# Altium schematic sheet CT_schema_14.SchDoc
size 519 x 434 mm
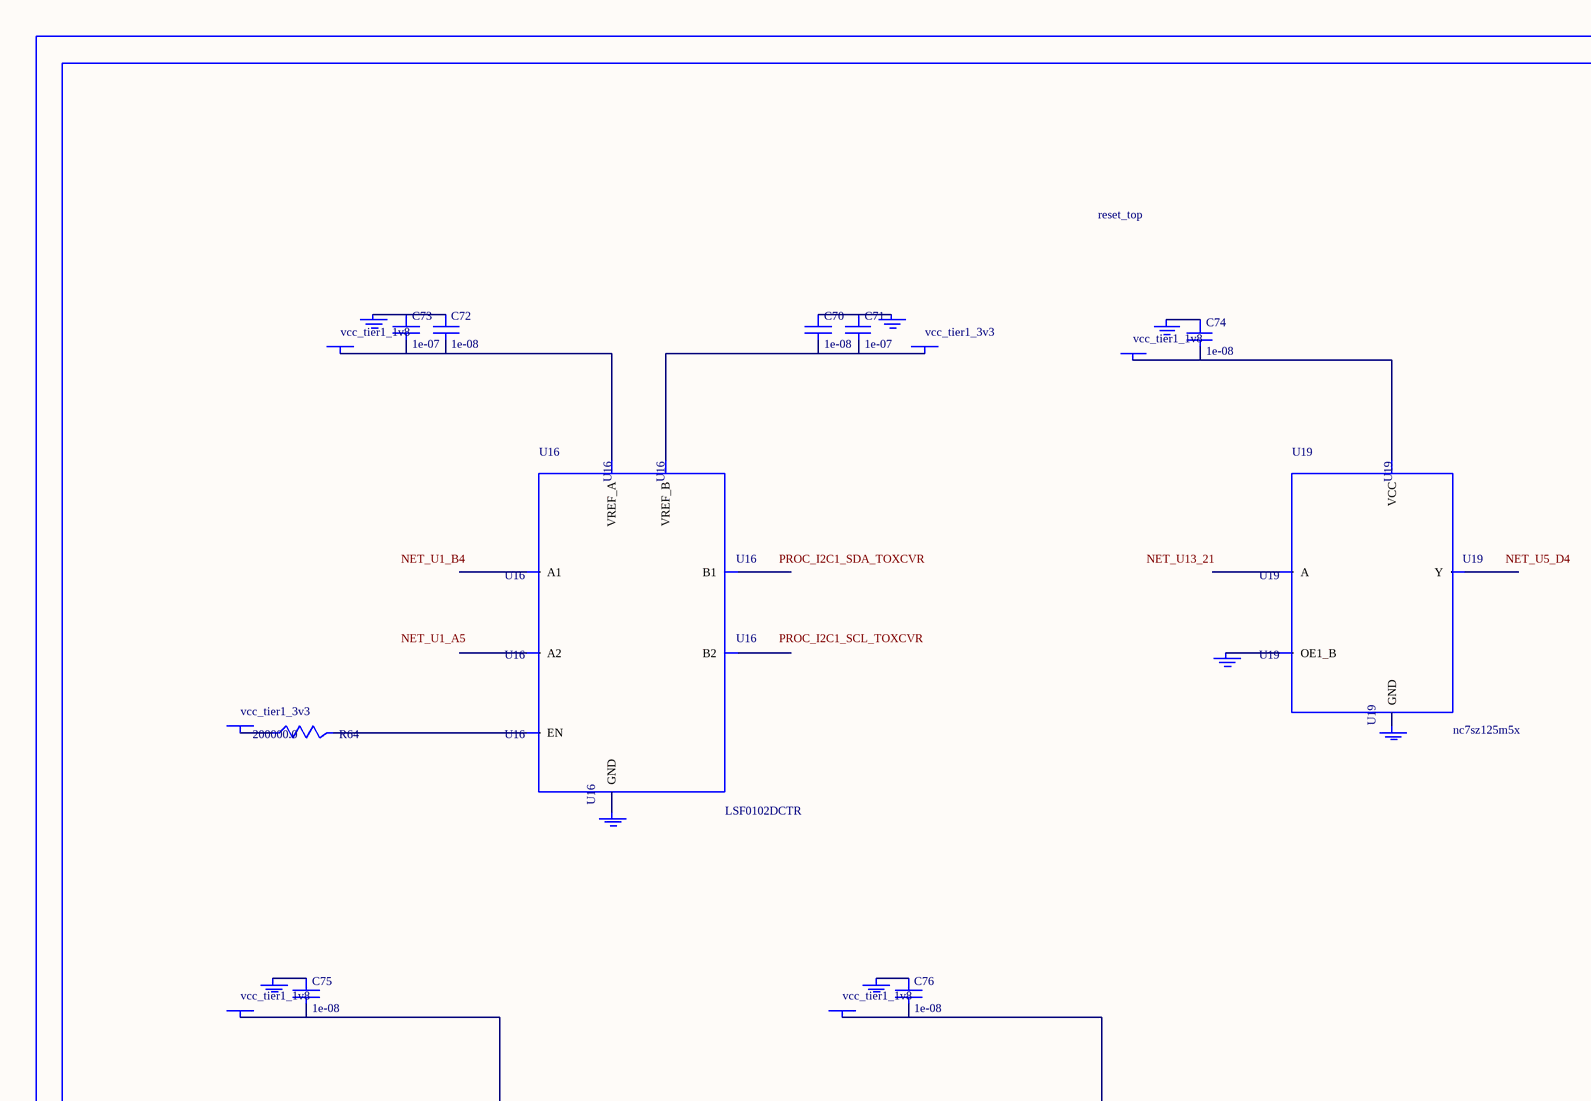
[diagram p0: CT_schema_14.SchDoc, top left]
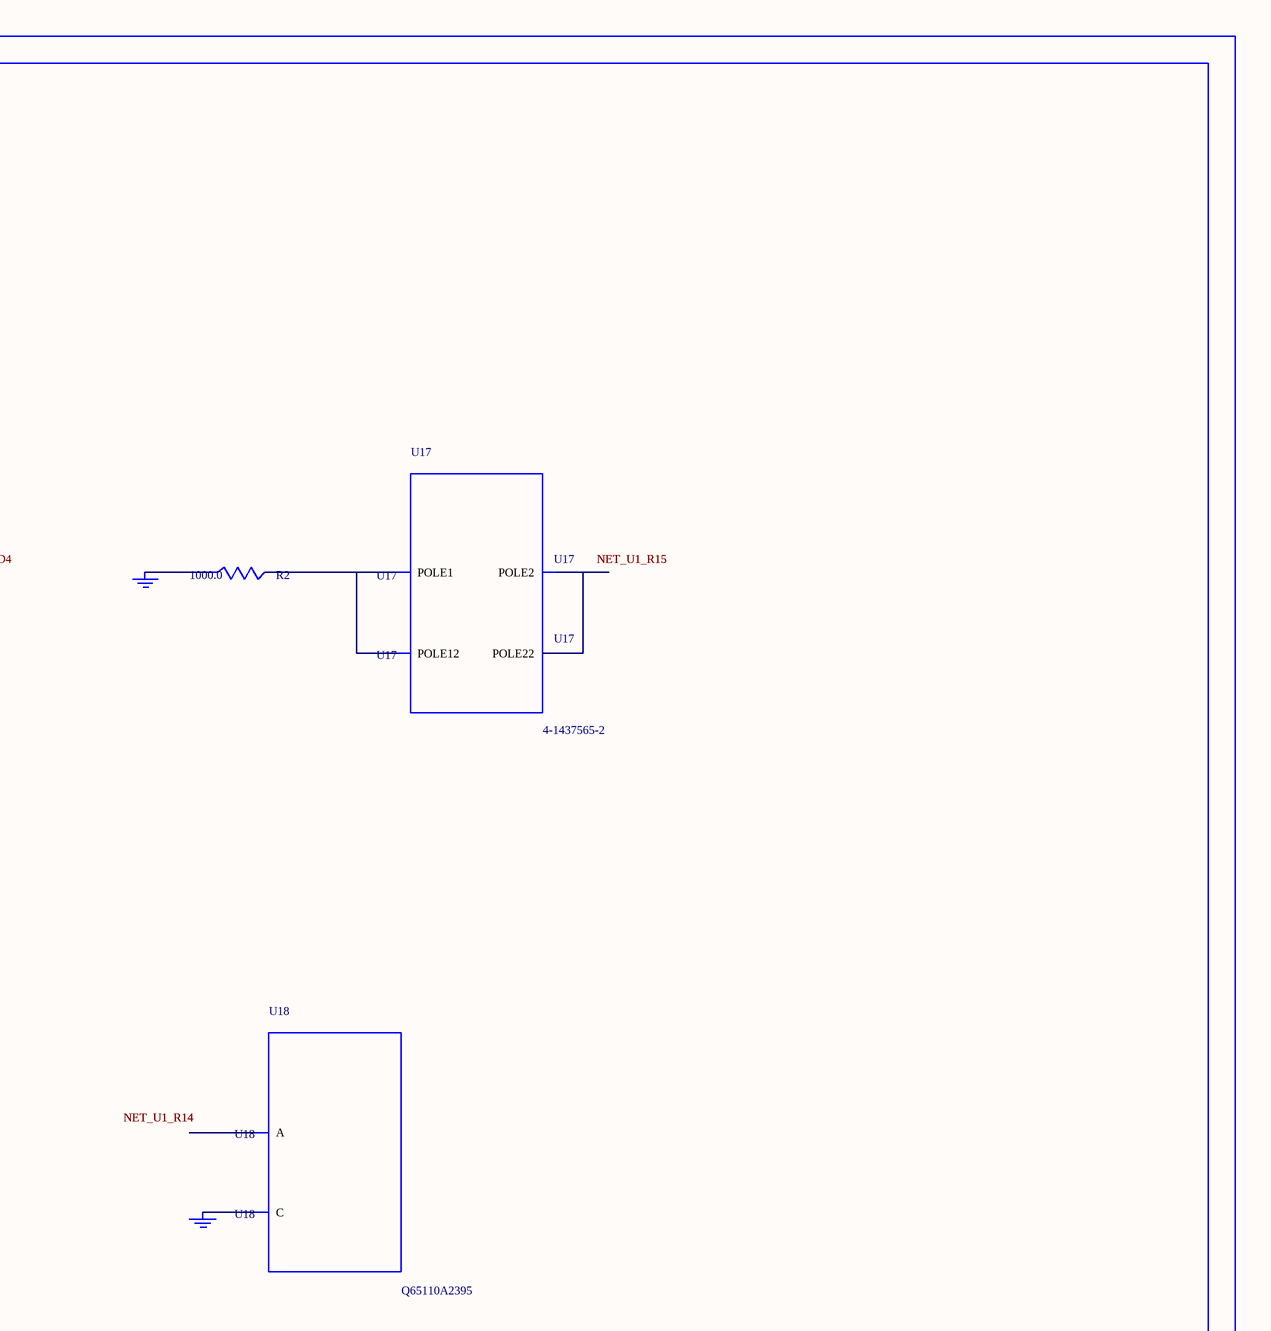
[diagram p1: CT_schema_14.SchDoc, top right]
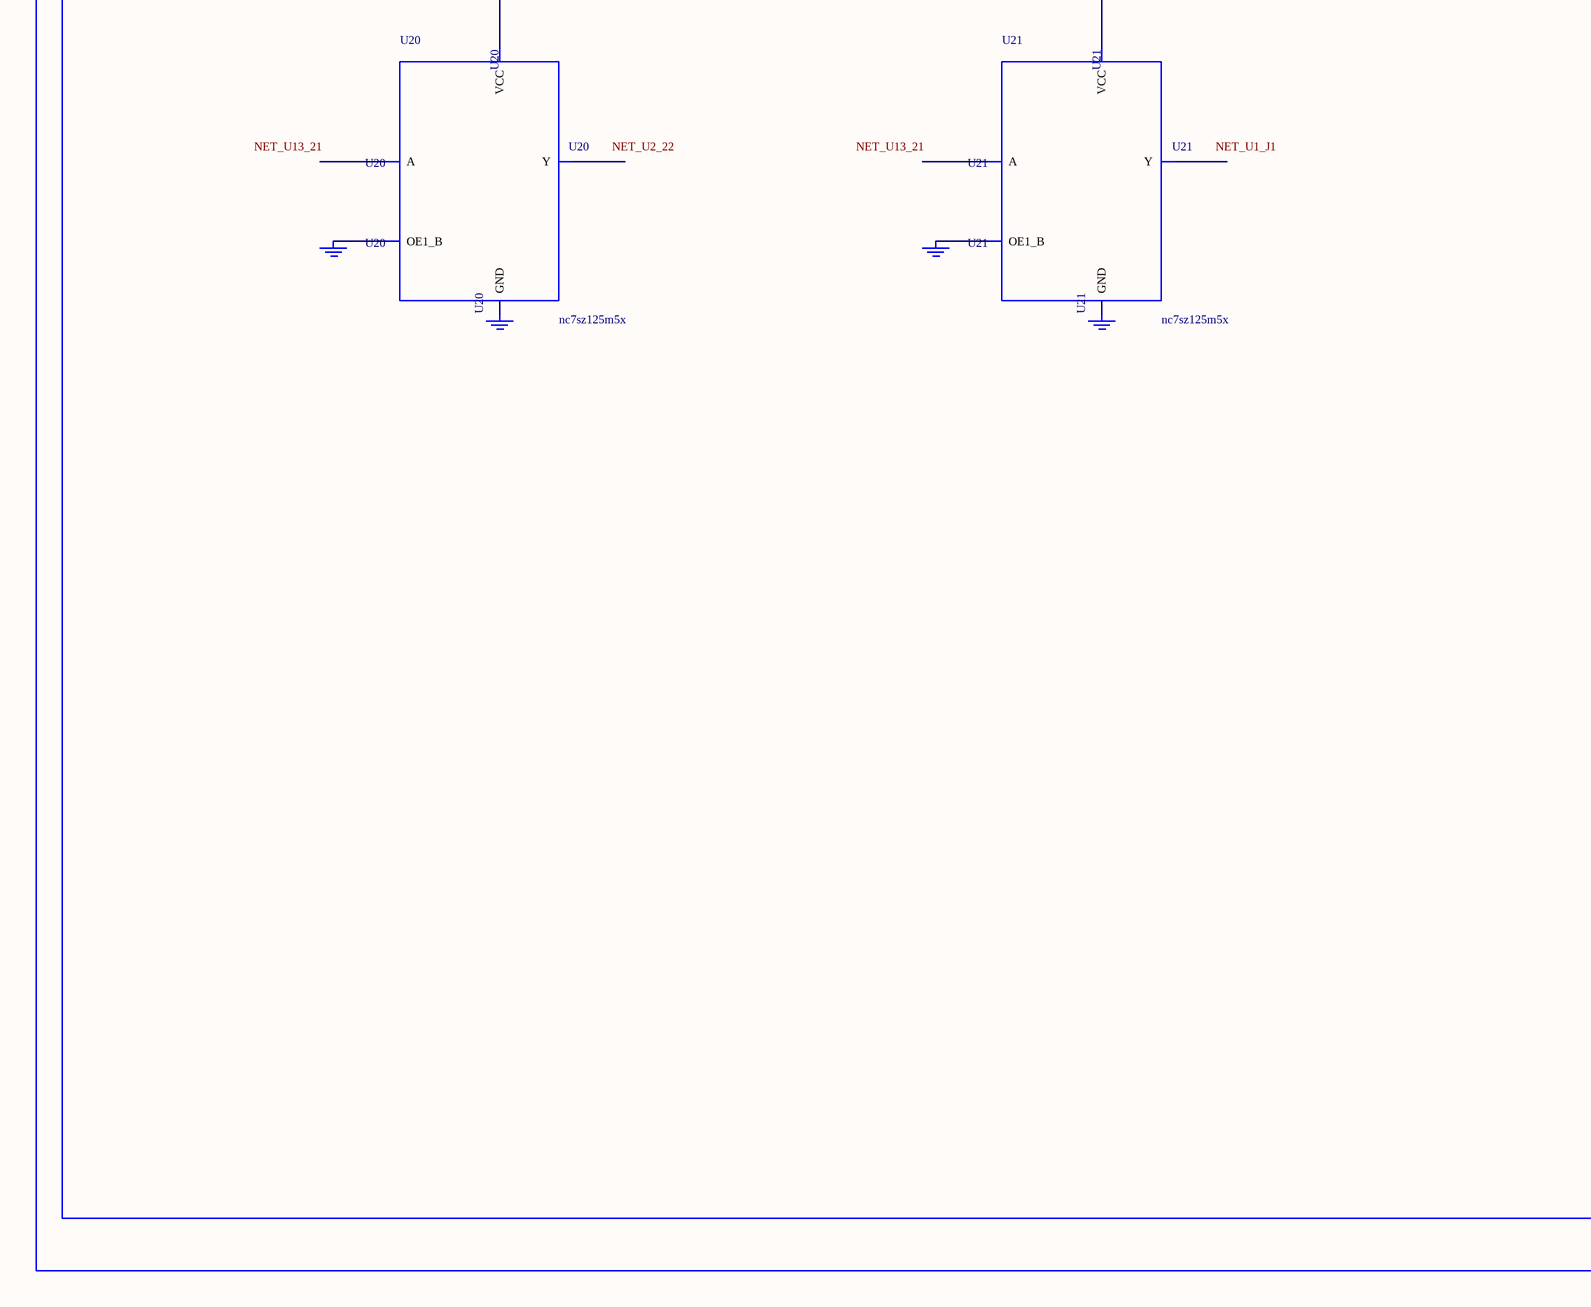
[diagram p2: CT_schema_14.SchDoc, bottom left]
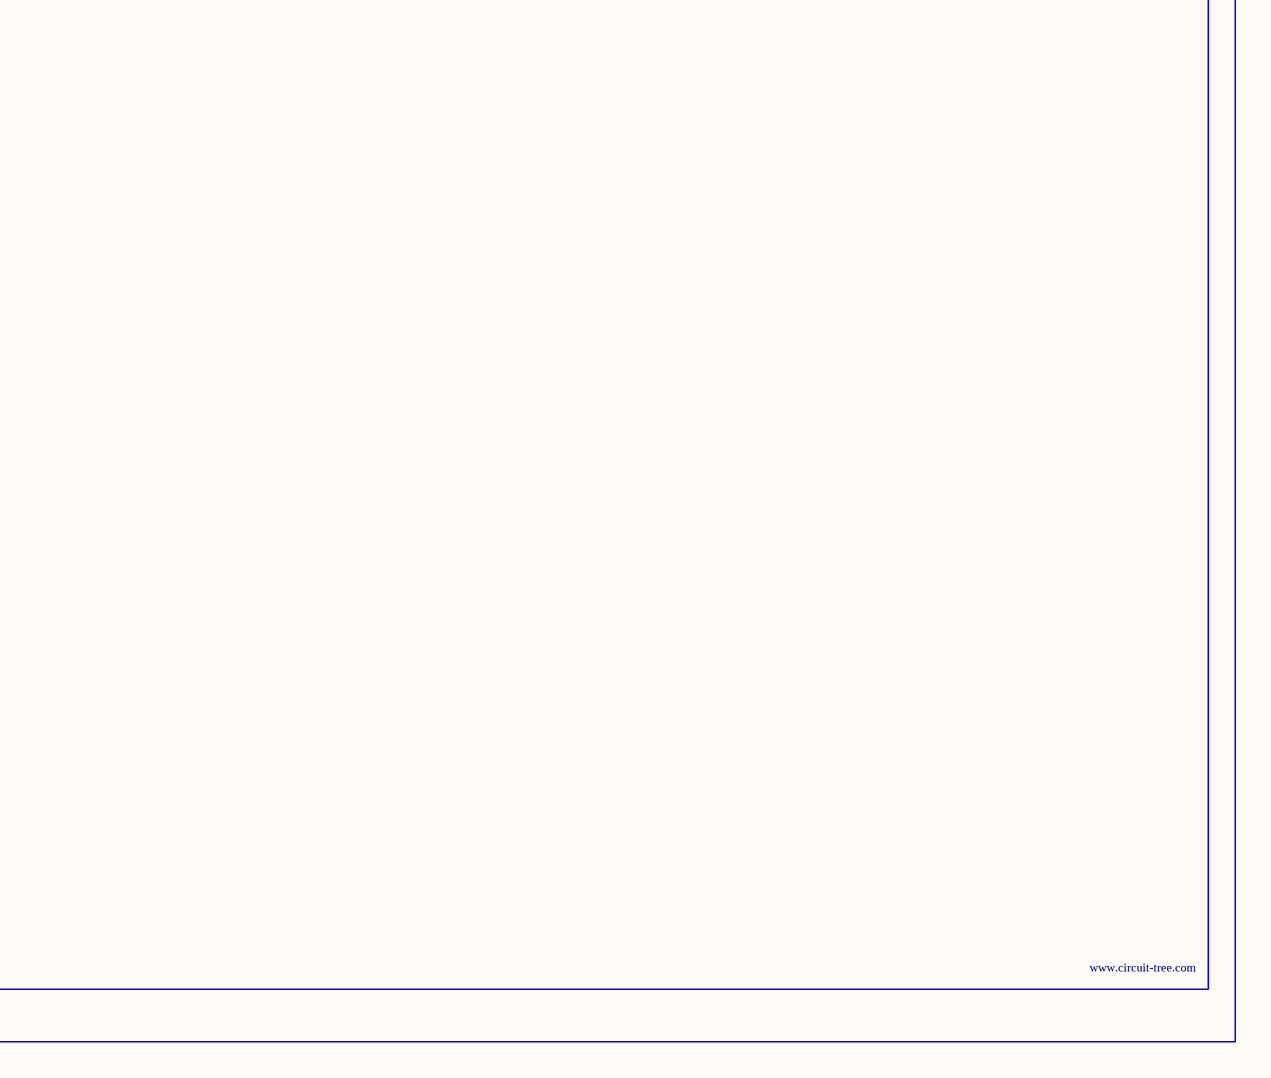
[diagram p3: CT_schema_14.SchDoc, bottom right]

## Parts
BORDER13  (no value)
C70  1e-08  [C0402]
C71  1e-07  [C0402]
C72  1e-08  [C0402]
C73  1e-07  [C0402]
C74  1e-08  [C0402]
C75  1e-08  [C0402]
C76  1e-08  [C0402]
GND_INSTANCE_13_0  (no value)
GND_INSTANCE_13_1  (no value)
GND_INSTANCE_13_2  (no value)
GND_INSTANCE_13_3  (no value)
GND_INSTANCE_13_4  (no value)
GND_INSTANCE_13_5  (no value)
GND_INSTANCE_13_6  (no value)
GND_INSTANCE_13_7  (no value)
GND_INSTANCE_13_8  (no value)
GND_INSTANCE_13_9  (no value)
GND_INSTANCE_13_10  (no value)
GND_INSTANCE_13_11  (no value)
GND_INSTANCE_13_12  (no value)
GND_INSTANCE_13_13  (no value)
POWER_INSTANCE_13_0  vcc_tier1_1v8
POWER_INSTANCE_13_1  vcc_tier1_3v3
POWER_INSTANCE_13_2  vcc_tier1_3v3
POWER_INSTANCE_13_3  vcc_tier1_1v8
POWER_INSTANCE_13_4  vcc_tier1_1v8
POWER_INSTANCE_13_5  vcc_tier1_1v8
R2  1000.0  [R0603]
R64  200000.0  [R0603]
U16  LSF0102DCTR  [DCU0008A_N]
U17  4-1437565-2  [SW_4-1437565-2]
U18  Q65110A2395  [LGM67K-G1J2-24-Z]
U19  nc7sz125m5x  [NC7SZ125M5X]
U20  nc7sz125m5x  [NC7SZ125M5X]
U21  nc7sz125m5x  [NC7SZ125M5X]

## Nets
NetC70_1: C70.1 C71.1 GND_INSTANCE_13_1.0(GND)
NetC70_2: C70.2 C71.2 POWER_INSTANCE_13_1.0(PWR) U16.7(VREF_B)
NetC72_1: C72.1 C73.1 GND_INSTANCE_13_0.0(GND)
NetC72_2: C72.2 C73.2 POWER_INSTANCE_13_0.0(PWR) U16.2(VREF_A)
NetC74_1: C74.1 GND_INSTANCE_13_5.0(GND)
NetC74_2: C74.2 POWER_INSTANCE_13_3.0(PWR) U19.5(VCC)
NetC75_1: C75.1 GND_INSTANCE_13_8.0(GND)
NetC75_2: C75.2 POWER_INSTANCE_13_4.0(PWR) U20.5(VCC)
NetC76_1: C76.1 GND_INSTANCE_13_11.0(GND)
NetC76_2: C76.2 POWER_INSTANCE_13_5.0(PWR) U21.5(VCC)
NetGND_INSTANCE_13_2_0: GND_INSTANCE_13_2.0(GND) U16.1(GND)
NetGND_INSTANCE_13_3_0: GND_INSTANCE_13_3.0(GND) R2.1
NetGND_INSTANCE_13_4_0: GND_INSTANCE_13_4.0(GND) U18.C
NetGND_INSTANCE_13_6_0: GND_INSTANCE_13_6.0(GND) U19.1(OE1_B)
NetGND_INSTANCE_13_7_0: GND_INSTANCE_13_7.0(GND) U19.3(GND)
NetGND_INSTANCE_13_9_0: GND_INSTANCE_13_9.0(GND) U20.1(OE1_B)
NetGND_INSTANCE_13_10_0: GND_INSTANCE_13_10.0(GND) U20.3(GND)
NetGND_INSTANCE_13_12_0: GND_INSTANCE_13_12.0(GND) U21.1(OE1_B)
NetGND_INSTANCE_13_13_0: GND_INSTANCE_13_13.0(GND) U21.3(GND)
NetPOWER_INSTANCE_13_2_0: POWER_INSTANCE_13_2.0(PWR) R64.1
NetR2_2: R2.2 U17.1(POLE1) U17.2(POLE12)
NetR64_2: R64.2 U16.8(EN)
NetU17_3: U17.3(POLE2) U17.4(POLE22)

Not connected (* = marked no-connect by the designer): U16 3(A1) 4(A2) 5(B2) 6(B1); U18 A; U19 2(A) 4(Y); U20 2(A) 4(Y); U21 2(A) 4(Y)

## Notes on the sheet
- Labels drawn without touching a wire or pin: NET_U1_A5, NET_U1_B4, NET_U1_J1, NET_U2_22, NET_U5_D4, NET_U13_21, PROC_I2C1_SCL_TOXCVR, PROC_I2C1_SDA_TOXCVR

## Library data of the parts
BORDER13 = BORDER_PAGE13
C70 C72 C74-C76 = C0402C103K3RAC
C71 C73 = C0402C104K3RACTU
GND_INSTANCE_13_0-GND_INSTANCE_13_13 = GND
POWER_INSTANCE_13_0-POWER_INSTANCE_13_5 = PWR
R2 = RC0603JR-071KL
R64 = RC0603JR-07200KL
